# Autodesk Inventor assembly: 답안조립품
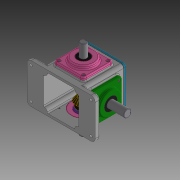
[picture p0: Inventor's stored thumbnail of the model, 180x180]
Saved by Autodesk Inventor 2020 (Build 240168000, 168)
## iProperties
Created: 2021-11
Part Number: 답안조립품
Document SubType Name: Assembly
Designer: user
Mass: 3235.88 g
Surface Area: 2651.66 cm^2
Volume: 866.536 cm^3
Density: 3.73427 g/cm^3
Author: user
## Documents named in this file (16)
- C:\Users\user\Desktop\611112V1003\답안조립품.iam
- C:\Users\user\Desktop\611112V1003\개스킷.ipt
- C:\Users\user\Desktop\611112V1003\메인베벨기어.ipt
- C:\Users\user\Desktop\611112V1003\메인축.ipt
- C:\Users\user\Desktop\611112V1003\메인커버.ipt
- C:\Users\user\Desktop\611112V1003\베어링 6203.ipt
- C:\Users\user\Desktop\611112V1003\베어링 6204.ipt
- C:\Users\user\Desktop\611112V1003\본체.ipt
- C:\Users\user\Desktop\611112V1003\볼트 M4.ipt
- C:\Users\user\Desktop\611112V1003\상부커버.ipt
- C:\Users\user\Desktop\611112V1003\서브베벨기어.ipt
- C:\Users\user\Desktop\611112V1003\서브축.ipt
- C:\Users\user\Desktop\611112V1003\서브커버.ipt
- C:\Users\user\Desktop\611112V1003\오일 실 17 32 8.ipt
- C:\Users\user\Desktop\611112V1003\오일 실 20 35 8.ipt
- C:\Users\user\Desktop\611112V1003\키 4x4.ipt
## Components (1 placed, 1 different names)
1. 개스킷:1
